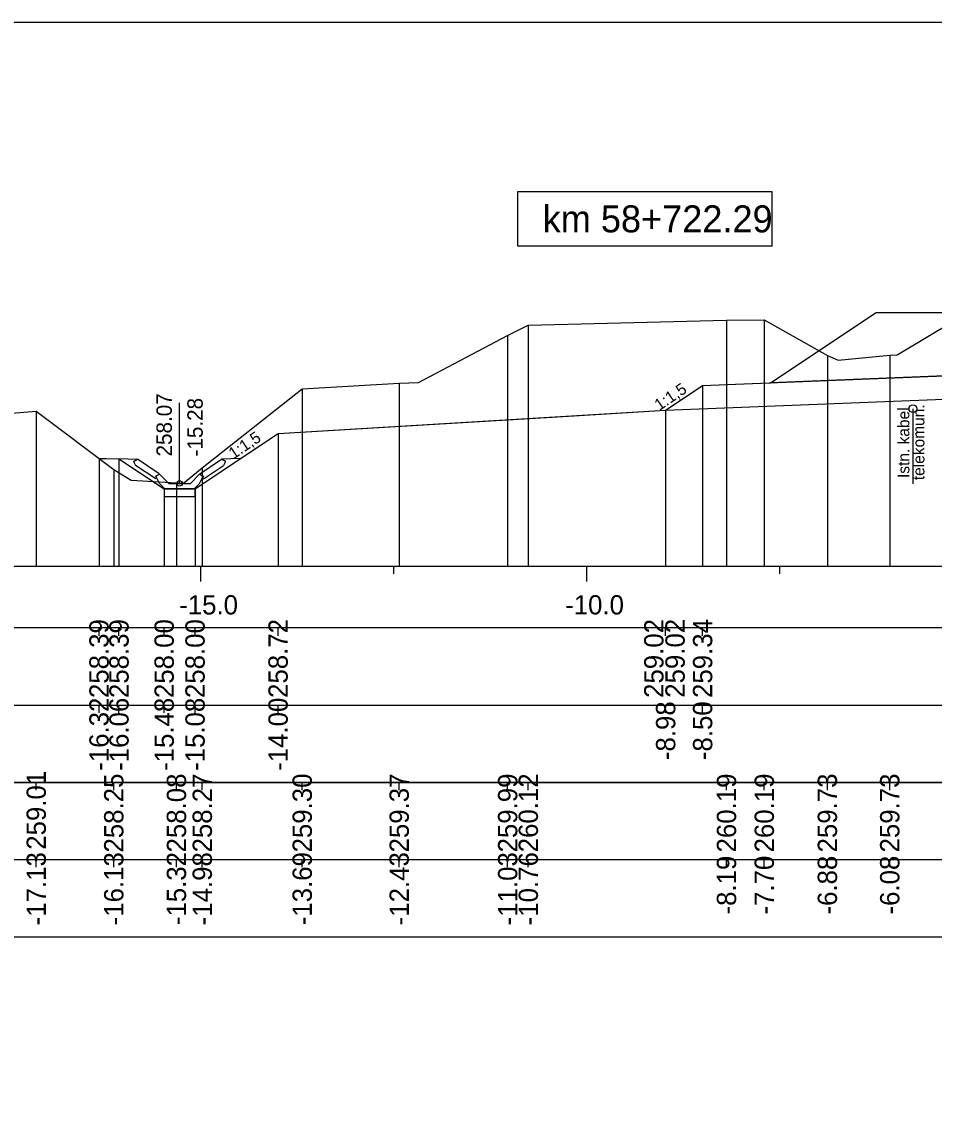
# Model space of a CAD drawing. Extents: x 6516023 to 6560129, y 5513077 to 5529206.
# Drawn here: x 6517020.4 to 6517032.21, y 5514532.41 to 5514546.66 of the extents above; entities that cross this region are included whole.
import ezdxf

# ---------------------------------------------------------------- set-up
doc = ezdxf.new("R2010")
doc.units = 0
for name, color, linetype in [('IR_default', 7, 'Continuous'), ('TOR_PRZEK_P-kable', 7, 'Continuous'), ('TOR_PRZEK_P-komponent', 7, 'Continuous'), ('TOR_PRZEK_P-odwodnienie', 7, 'Continuous'), ('TOR_PRZEK_P-opisy', 7, 'Continuous'), ('TOR_PRZEK_P-tabelka istniejace', 7, 'Continuous'), ('TOR_PRZEK_P-tabelka projektowane', 7, 'Continuous'), ('TOR_PRZEK_P-teren istniejacy', 7, 'Continuous'), ('TOR_PRZEK_P-uklad odniesienia', 7, 'Continuous'), ('TOR_PRZEK_P-warstwa ochronna I', 7, 'Continuous'), ('TOR_PRZEK_P-warstwa ochronna II', 7, 'Continuous'), ('TOR_RAMKI-ramka+tabelka 1', 7, 'Continuous')]:
    doc.layers.add(name, color=color, linetype=linetype)

msp = doc.modelspace()

# ---------------------------------------------------------------- linework, layer by layer
at = {"layer": 'IR_default'}
msp.add_lwpolyline([(6517021.393, 5514541.001), (6517021.487, 5514541), (6517021.652, 5514540.998), (6517021.676, 5514540.982), (6517021.742, 5514540.938), (6517021.876, 5514540.849), (6517022.237, 5514540.608), (6517022.345, 5514540.608), (6517022.637, 5514540.608), (6517022.928, 5514540.803), (6517023.713, 5514541.326), (6517027.263, 5514541.539), (6517028.734, 5514541.627), (6517029.04, 5514541.831), (6517029.213, 5514541.946), (6517029.854, 5514541.972), (6517030.093, 5514541.981), (6517031.092, 5514542.647), (6517031.463, 5514542.895), (6517034.015, 5514542.895)], dxfattribs=at)
at = {"layer": 'TOR_PRZEK_P-kable'}
msp.add_line((6517031.937, 5514541.647), (6517031.937, 5514540.673), dxfattribs=at)
msp.add_circle((6517031.937, 5514541.647), 0.05, dxfattribs=at)
at = {"layer": 'TOR_PRZEK_P-komponent'}
msp.add_lwpolyline([(6517031.463, 5514542.895), (6517034.963, 5514542.895), (6517035.963, 5514542.895), (6517039.463, 5514542.895), (6517040.013, 5514542.896), (6517043.513, 5514542.896), (6517044.598, 5514542.172), (6517041.013, 5514542.316), (6517039.763, 5514542.366), (6517039.713, 5514542.366), (6517038.463, 5514542.316), (6517037.713, 5514542.286), (6517035.463, 5514542.196), (6517033.213, 5514542.106), (6517030.093, 5514541.981)], close=True, dxfattribs=at)
at = {"layer": 'TOR_PRZEK_P-odwodnienie'}
for p, q in [((6517022.437, 5514540.678), (6517022.437, 5514541.722)), ((6517022.172, 5514540.804), (6517021.892, 5514540.991)), ((6517022.701, 5514540.804), (6517022.982, 5514540.991)), ((6517022.128, 5514540.738), (6517021.867, 5514540.912)), ((6517022.746, 5514540.738), (6517023.007, 5514540.912)), ((6517022.139, 5514540.754), (6517022.128, 5514540.738)), ((6517022.129, 5514540.773), (6517022.177, 5514540.797)), ((6517022.172, 5514540.804), (6517022.164, 5514540.792)), ((6517022.297, 5514540.678), (6517022.177, 5514540.797)), ((6517022.297, 5514540.678), (6517022.577, 5514540.678)), ((6517022.577, 5514540.678), (6517022.697, 5514540.797)), ((6517022.697, 5514540.797), (6517022.744, 5514540.773)), ((6517022.701, 5514540.804), (6517022.71, 5514540.792)), ((6517022.735, 5514540.754), (6517022.746, 5514540.738)), ((6517022.247, 5514540.608), (6517022.627, 5514540.608))]:
    msp.add_line(p, q, dxfattribs=at)
for points in [[(6517021.645, 5514541.003), (6517021.892, 5514540.991)], [(6517021.842, 5514540.964), (6517021.892, 5514540.991)], [(6517021.842, 5514540.964), (6517021.867, 5514540.912)], [(6517023.228, 5514541.003), (6517022.982, 5514540.991)], [(6517023.032, 5514540.964), (6517022.982, 5514540.991)], [(6517023.032, 5514540.964), (6517023.007, 5514540.912)], [(6517022.164, 5514540.792), (6517022.129, 5514540.773)], [(6517022.177, 5514540.678), (6517022.129, 5514540.773)], [(6517022.129, 5514540.773), (6517022.139, 5514540.754)], [(6517022.247, 5514540.608), (6517022.177, 5514540.678)], [(6517022.627, 5514540.608), (6517022.697, 5514540.678)], [(6517022.697, 5514540.678), (6517022.744, 5514540.773)], [(6517022.71, 5514540.792), (6517022.745, 5514540.773)], [(6517022.745, 5514540.773), (6517022.735, 5514540.754)], [(6517022.237, 5514540.608), (6517022.236, 5514540.609), (6517022.237, 5514540.608), (6517022.236, 5514540.608), (6517022.237, 5514540.608), (6517022.237, 5514540.608), (6517022.237, 5514540.608), (6517022.237, 5514540.609)], [(6517022.237, 5514540.608), (6517022.236, 5514540.609), (6517022.237, 5514540.608), (6517022.236, 5514540.608), (6517022.237, 5514540.608), (6517022.237, 5514540.608), (6517022.237, 5514540.608), (6517022.237, 5514540.609)], [(6517022.637, 5514540.608), (6517022.237, 5514540.608), (6517022.237, 5514540.508), (6517022.637, 5514540.508), (6517022.637, 5514540.608)], [(6517022.637, 5514540.608), (6517022.636, 5514540.609), (6517022.637, 5514540.608), (6517022.636, 5514540.608), (6517022.637, 5514540.608), (6517022.637, 5514540.608), (6517022.637, 5514540.608), (6517022.637, 5514540.609)], [(6517022.637, 5514540.608), (6517022.636, 5514540.609), (6517022.637, 5514540.608), (6517022.636, 5514540.608), (6517022.637, 5514540.608), (6517022.637, 5514540.608), (6517022.637, 5514540.608), (6517022.637, 5514540.609)]]:
    msp.add_lwpolyline(points, dxfattribs=at)
msp.add_circle((6517022.437, 5514540.678), 0.035, dxfattribs=at)
at = {"layer": 'TOR_PRZEK_P-tabelka istniejace'}
for p, q in [((6517020.58, 5514536.706), (6517020.58, 5514536.806)), ((6517021.584, 5514536.706), (6517021.584, 5514536.806)), ((6517022.396, 5514536.706), (6517022.396, 5514536.806)), ((6517022.731, 5514536.706), (6517022.731, 5514536.806)), ((6517024.026, 5514536.706), (6517024.026, 5514536.806)), ((6517025.282, 5514536.706), (6517025.282, 5514536.806)), ((6517026.687, 5514536.706), (6517026.687, 5514536.806)), ((6517026.955, 5514536.706), (6517026.955, 5514536.806)), ((6517029.522, 5514536.706), (6517029.522, 5514536.806)), ((6517030.012, 5514536.706), (6517030.012, 5514536.806)), ((6517030.829, 5514536.706), (6517030.829, 5514536.806)), ((6517031.637, 5514536.706), (6517031.637, 5514536.806)), ((6516996.663, 5514535.806), (6517080.463, 5514535.806)), ((6517020.58, 5514535.706), (6517020.58, 5514535.806)), ((6517021.584, 5514535.706), (6517021.584, 5514535.806)), ((6517022.396, 5514535.706), (6517022.396, 5514535.806)), ((6517022.731, 5514535.706), (6517022.731, 5514535.806)), ((6517024.026, 5514535.706), (6517024.026, 5514535.806)), ((6517025.282, 5514535.706), (6517025.282, 5514535.806)), ((6517026.687, 5514535.706), (6517026.687, 5514535.806)), ((6517026.955, 5514535.706), (6517026.955, 5514535.806)), ((6517029.522, 5514535.706), (6517029.522, 5514535.806)), ((6517030.012, 5514535.706), (6517030.012, 5514535.806)), ((6517030.829, 5514535.706), (6517030.829, 5514535.806)), ((6517031.637, 5514535.706), (6517031.637, 5514535.806))]:
    msp.add_line(p, q, dxfattribs=at)
for points in [[(6517026.955, 5514542.729), (6517026.955, 5514539.806), (6517026.955, 5514539.676), (6517026.955, 5514539.606)], [(6517029.522, 5514542.794), (6517029.522, 5514539.806), (6517029.522, 5514539.676), (6517029.522, 5514539.606)], [(6517030.012, 5514542.798), (6517030.012, 5514539.806), (6517030.012, 5514539.676), (6517030.012, 5514539.606)], [(6517026.687, 5514542.595), (6517026.687, 5514539.806), (6517026.687, 5514539.676), (6517026.687, 5514539.606)], [(6517030.829, 5514542.335), (6517030.829, 5514539.806), (6517030.829, 5514539.676), (6517030.829, 5514539.606)], [(6517031.637, 5514542.339), (6517031.637, 5514539.806), (6517031.637, 5514539.676), (6517031.637, 5514539.606)], [(6517025.282, 5514541.977), (6517025.282, 5514539.806), (6517025.282, 5514539.676), (6517025.282, 5514539.606)], [(6517024.026, 5514541.904), (6517024.026, 5514539.806), (6517024.026, 5514539.676), (6517024.026, 5514539.606)], [(6517020.58, 5514541.615), (6517020.58, 5514539.806), (6517020.58, 5514539.676), (6517020.58, 5514539.606)], [(6517021.584, 5514540.857), (6517021.584, 5514539.806), (6517021.584, 5514539.676), (6517021.584, 5514539.606)], [(6517022.731, 5514540.88), (6517022.731, 5514539.806), (6517022.731, 5514539.676), (6517022.731, 5514539.606)], [(6517022.396, 5514540.686), (6517022.396, 5514539.806), (6517022.396, 5514539.676), (6517022.396, 5514539.606)]]:
    msp.add_lwpolyline(points, dxfattribs=at)
msp.add_lwpolyline([(6516996.663, 5514536.806), (6516996.663, 5514534.806), (6517080.463, 5514534.806), (6517080.463, 5514536.806)], close=True, dxfattribs=at)
at = {"layer": 'TOR_PRZEK_P-tabelka projektowane'}
for p, q in [((6517021.393, 5514538.706), (6517021.393, 5514538.806)), ((6517021.652, 5514538.706), (6517021.652, 5514538.806)), ((6517022.237, 5514538.706), (6517022.237, 5514538.806)), ((6517022.637, 5514538.706), (6517022.637, 5514538.806)), ((6517023.713, 5514538.706), (6517023.713, 5514538.806)), ((6517028.734, 5514538.706), (6517028.734, 5514538.806)), ((6517028.734, 5514538.706), (6517028.734, 5514538.806)), ((6517029.213, 5514538.706), (6517029.213, 5514538.806)), ((6516996.663, 5514537.806), (6517080.463, 5514537.806)), ((6517021.393, 5514537.706), (6517021.393, 5514537.806)), ((6517021.652, 5514537.706), (6517021.652, 5514537.806)), ((6517022.237, 5514537.706), (6517022.237, 5514537.806)), ((6517022.637, 5514537.706), (6517022.637, 5514537.806)), ((6517023.713, 5514537.706), (6517023.713, 5514537.806)), ((6517028.734, 5514537.706), (6517028.734, 5514537.806)), ((6517028.734, 5514537.706), (6517028.734, 5514537.806)), ((6517029.213, 5514537.706), (6517029.213, 5514537.806))]:
    msp.add_line(p, q, dxfattribs=at)
for points in [[(6517029.213, 5514541.946), (6517029.213, 5514539.806), (6517029.213, 5514539.676), (6517029.213, 5514539.606)], [(6517028.734, 5514541.627), (6517028.734, 5514539.806), (6517028.734, 5514539.676), (6517028.734, 5514539.606)], [(6517028.734, 5514541.627), (6517028.734, 5514539.806), (6517028.734, 5514539.676), (6517028.734, 5514539.606)], [(6517023.713, 5514541.326), (6517023.713, 5514539.806), (6517023.713, 5514539.676), (6517023.713, 5514539.606)], [(6517021.393, 5514541.001), (6517021.393, 5514539.806), (6517021.393, 5514539.676), (6517021.393, 5514539.606)], [(6517021.652, 5514540.998), (6517021.652, 5514539.806), (6517021.652, 5514539.676), (6517021.652, 5514539.606)], [(6517022.237, 5514540.608), (6517022.237, 5514539.806), (6517022.237, 5514539.676), (6517022.237, 5514539.606)], [(6517022.637, 5514540.608), (6517022.637, 5514539.806), (6517022.637, 5514539.676), (6517022.637, 5514539.606)]]:
    msp.add_lwpolyline(points, dxfattribs=at)
msp.add_lwpolyline([(6516996.663, 5514538.806), (6516996.663, 5514536.806), (6517080.463, 5514536.806), (6517080.463, 5514538.806)], close=True, dxfattribs=at)
at = {"layer": 'TOR_PRZEK_P-teren istniejacy'}
msp.add_lwpolyline([(6517019.987, 5514541.568), (6517020.58, 5514541.615), (6517021.584, 5514540.857), (6517021.811, 5514540.719), (6517022.396, 5514540.686), (6517022.486, 5514540.682), (6517022.731, 5514540.88), (6517024.026, 5514541.904), (6517025.282, 5514541.977), (6517025.531, 5514541.987), (6517026.687, 5514542.595), (6517026.955, 5514542.729), (6517029.522, 5514542.794), (6517030.012, 5514542.798), (6517030.829, 5514542.335), (6517030.967, 5514542.274), (6517031.637, 5514542.339), (6517031.735, 5514542.344), (6517032.462, 5514542.78)], dxfattribs=at)
at = {"layer": 'TOR_PRZEK_P-uklad odniesienia'}
for p, q in [((6517000.463, 5514539.606), (6517080.463, 5514539.606)), ((6517022.713, 5514539.406), (6517022.713, 5514539.606)), ((6517025.213, 5514539.506), (6517025.213, 5514539.606)), ((6517027.713, 5514539.406), (6517027.713, 5514539.606)), ((6517030.213, 5514539.506), (6517030.213, 5514539.606))]:
    msp.add_line(p, q, dxfattribs=at)
msp.add_lwpolyline([(6517030.113, 5514544.456), (6517026.813, 5514544.456), (6517026.813, 5514543.756), (6517030.113, 5514543.756)], close=True, dxfattribs=at)
at = {"layer": 'TOR_PRZEK_P-warstwa ochronna I'}
msp.add_lwpolyline([(6517028.734, 5514541.627), (6517033.213, 5514541.806), (6517035.463, 5514541.896), (6517037.713, 5514541.986), (6517039.713, 5514542.066), (6517039.763, 5514542.066), (6517041.013, 5514542.016), (6517041.763, 5514541.986), (6517046.715, 5514541.787)], dxfattribs=at)
at = {"layer": 'TOR_PRZEK_P-warstwa ochronna II'}
msp.add_lwpolyline([(6517021.393, 5514541.001), (6517021.652, 5514540.998), (6517022.237, 5514540.608), (6517022.637, 5514540.608), (6517023.713, 5514541.326), (6517028.734, 5514541.627), (6517029.213, 5514541.946), (6517033.213, 5514542.106), (6517035.463, 5514542.196), (6517037.713, 5514542.286), (6517038.463, 5514542.316), (6517039.713, 5514542.366), (6517039.763, 5514542.365), (6517041.013, 5514542.315), (6517041.763, 5514542.285), (6517046.063, 5514542.113), (6517046.933, 5514541.679), (6517049.433, 5514540.428), (6517049.833, 5514540.428), (6517050.688, 5514540.998), (6517053.112, 5514541.023)], dxfattribs=at)
at = {"layer": 'TOR_RAMKI-ramka+tabelka 1'}
msp.add_lwpolyline([(6516907.013, 5514546.656), (6517154.513, 5514546.656), (6517154.513, 5514518.156), (6516907.013, 5514518.156)], close=True, dxfattribs=at)

# ---------------------------------------------------------------- texts
at = {"layer": 'TOR_PRZEK_P-kable'}
for s, height, p in [('telekomun.', 0.15, (6517032.087, 5514540.721)), ('Istn. kabel', 0.14999, (6517031.892, 5514540.749))]:
    msp.add_text(s, height=height, rotation=90.0511, dxfattribs=at).set_placement(p)
at = {"layer": 'TOR_PRZEK_P-odwodnienie'}
for s, p in [('258.07', (6517022.337, 5514541.028)), ('-15.28', (6517022.737, 5514541.028))]:
    msp.add_text(s, height=0.2, rotation=90, dxfattribs=at).set_placement(p)
at = {"layer": 'TOR_PRZEK_P-opisy'}
for p in [(6517028.653, 5514541.616), (6517023.136, 5514540.988)]:
    msp.add_text('1:1,5', height=0.15, rotation=34.0701, dxfattribs=at).set_placement(p)
at = {"layer": 'TOR_PRZEK_P-tabelka istniejace'}
for s, p in [('259.01', (6517020.705, 5514535.933)), ('258.25', (6517021.709, 5514535.897)), ('258.08', (6517022.521, 5514535.898)), ('258.27', (6517022.856, 5514535.898)), ('259.30', (6517024.151, 5514535.898)), ('259.37', (6517025.407, 5514535.898)), ('259.99', (6517026.812, 5514535.898)), ('260.12', (6517027.08, 5514535.9)), ('260.19', (6517029.647, 5514535.898)), ('260.19', (6517030.137, 5514535.898)), ('259.73', (6517030.954, 5514535.898)), ('259.73', (6517031.762, 5514535.898)), ('-17.13', (6517020.705, 5514534.954)), ('-16.13', (6517021.709, 5514534.954)), ('-15.32', (6517022.521, 5514534.956)), ('-14.98', (6517022.856, 5514534.954)), ('-13.69', (6517024.151, 5514534.955)), ('-12.43', (6517025.407, 5514534.954)), ('-11.03', (6517026.812, 5514534.954)), ('-10.76', (6517027.08, 5514534.954)), ('-8.19', (6517029.647, 5514535.094)), ('-7.70', (6517030.137, 5514535.094)), ('-6.88', (6517030.954, 5514535.094)), ('-6.08', (6517031.762, 5514535.094))]:
    msp.add_text(s, height=0.25, rotation=90, dxfattribs=at).set_placement(p)
at = {"layer": 'TOR_PRZEK_P-tabelka projektowane'}
for s, p in [('258.39', (6517021.518, 5514537.898)), ('258.39', (6517021.777, 5514537.898)), ('258.00', (6517022.362, 5514537.898)), ('258.00', (6517022.762, 5514537.898)), ('258.72', (6517023.838, 5514537.9)), ('259.02', (6517028.706, 5514537.9)), ('259.02', (6517028.981, 5514537.902)), ('259.34', (6517029.338, 5514537.899)), ('-16.32', (6517021.518, 5514536.956)), ('-16.06', (6517021.777, 5514536.954)), ('-15.48', (6517022.362, 5514536.954)), ('-15.08', (6517022.762, 5514536.954)), ('-14.00', (6517023.838, 5514536.955)), ('-8.98', (6517028.859, 5514537.094)), ('-8.50', (6517029.338, 5514537.094))]:
    msp.add_text(s, height=0.25, rotation=90, dxfattribs=at).set_placement(p)
at = {"layer": 'TOR_PRZEK_P-uklad odniesienia'}
for s, height, p in [('km 58+722.29', 0.35, (6517027.141, 5514543.931)), ('-15.0', 0.25, (6517022.432, 5514538.981)), ('-10.0', 0.25, (6517027.432, 5514538.981))]:
    msp.add_text(s, height=height, dxfattribs=at).set_placement(p)

doc.saveas('drawing.dxf')
